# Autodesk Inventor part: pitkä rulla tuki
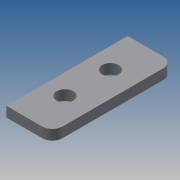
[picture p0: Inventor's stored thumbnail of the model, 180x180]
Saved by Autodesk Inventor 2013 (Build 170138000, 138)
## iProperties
Created: 2013-08
Part Number: pitkä rulla tuki
Material: Generic
Document SubType Name: Sheet Metal
Designer: Reko Tuppurainen
Density: 1 g/cm^3
Sheet Metal Rule: Default_mm
Author: Reko Tuppurainen
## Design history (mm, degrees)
node "Face1"
  sketch "Sketch1"
    geometry: L1 (-2.115, 26.56)-(57.885, 26.56); L2 (57.885, 26.56)-(57.885, -69.44); L3 (57.885, -69.44)-(-2.115, -69.44); L4 (-2.115, -69.44)-(-2.115, 26.56); 1 further point
    constraints: 8 end point, 2 parallel, 1 horizontal, 1 perpendicular
    dimensions: "d0" = 60 distance of L2.end L3.end; "d1" = 96 distance of L1.end L2.end
feature "Corner Round1" dims "d3" = 8
sketch "Sketch2"
  geometry: L1 (-2.115, 26.56)-(49.885, 26.56) reference; L2 (-2.115, -69.44)-(-2.115, 26.56) reference; L3 (49.885, -69.44)-(-2.115, -69.44) reference; C1 r 6.5 at (37.885, -3.44); C2 r 6.5 at (37.885, -39.44); 1 further point
  constraints: 2 centre point
  dimensions: "d4" = 13 diameter of C1; "d5" = 13 diameter of C2; "d6" = 30 distance from line of L1 C1.centre; "d7" = 30 distance from line of L3 C2.centre; "d8" = 40 distance from line of L2 C1.centre; "d9" = 40 distance from line of L2 C2.centre
cut "Cut1" sketch "Sketch2" dims "d10" = 8 (= Thickness), "d11" = 0
sketch "Sketch3"
  geometry: L1 (-2.115, 26.56)-(49.885, 26.56) reference; L2 (-2.115, -69.44)-(-2.115, 26.56) reference; L3 (49.885, -69.44)-(-2.115, -69.44) reference; L4 (21.558, -69.44)-(21.558, 26.56); 1 further point
  constraints: 2 end point, 2 point on line, 1 perpendicular
cut "Cut2" sketch "Sketch3" dims "d12" = 8 (= Thickness), "d13" = 0
body "Solid1"
face "Plate1" dims "Thickness" = 8 (derived)
other parameters: "BendRadius" = 8 (= Thickness), "BendReliefWidth" = 8 (= Thickness), "BendReliefDepth" = 4 (= 0.5 x Thickness), "CornerReliefSize" = 32 (= 4 x Thickness), "SeamGap" = 0.01, "MinimumRemnant" = 16 (= 2 x Thickness), "TransitionRadius" = 8 (= BendRadius), "JacobiRadiusSize" = 8 (= BendRadius), "GapSize" = 8 (= Thickness), "d2" = 8 (= BendRadius)
